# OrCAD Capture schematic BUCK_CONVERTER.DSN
size A
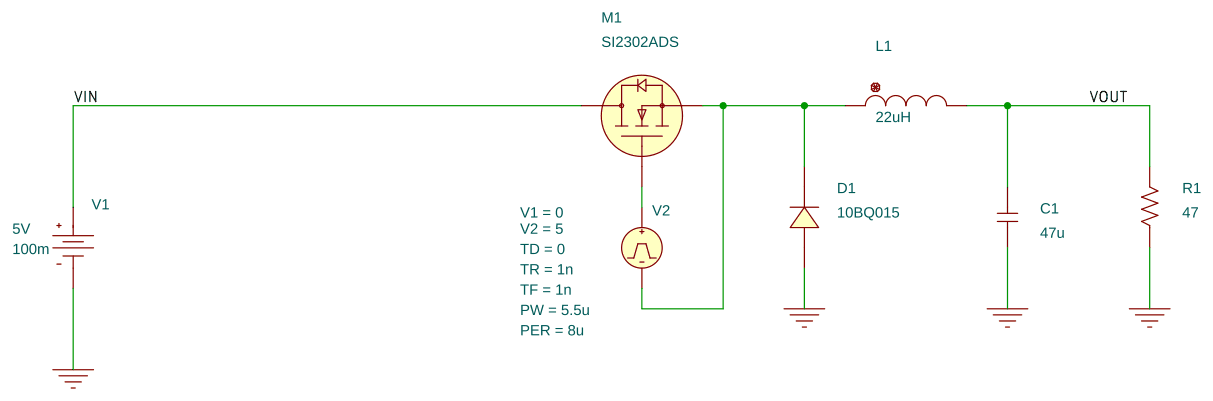
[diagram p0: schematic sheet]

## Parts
C1  47u  [cap196]
D1  10BQ015  [DIOMELF3521N]
L1  22uH  [DISC350x175LS200x100034]
M1  SI2302ADS  [to236aasot23]
R1  47  [AXRC05]
V1  VDC
V2  VPULSE

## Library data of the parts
C1 = C
D1 = 10BQ015
L1 = L
M1 = Si2302ADS
R1 = R
V1 = VDCR: AppProp: DC$Voltage$1$-1; DC: 5V; RDC: 100m
V2 = VPULSE: PER: 8u; PW: 5.5u; TD: 0; TF: 1n; TR: 1n; V1: 0; V2: 5

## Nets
VIN: M1.3(D) V1.0(+)
0: C1.1 D1.1(A) R1.1 V1.1(-)
VOUT: C1.2 L1.2 R1.2
N00145: M1.1(G) V2.1(+)
N00149: D1.2(C) L1.1 M1.2(S) V2.2(-)
